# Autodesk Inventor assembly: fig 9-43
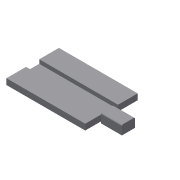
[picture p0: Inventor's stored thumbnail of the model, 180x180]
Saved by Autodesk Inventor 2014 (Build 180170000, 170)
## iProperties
Created: 2013-07
Part Number: fig 9-43
Document SubType Name: Assembly
Designer: CADCIM
Author: CADCIM
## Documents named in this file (3)
- E:\APS\Autodesk Inventor 2014-Project\inventor_2014_partfiles\Inventor_2014_prt\c09_Inv_2014_prt\c09_inv_2014_prt\fig 9-43.iam
- E:\APS\Autodesk Inventor 2014-Project\inventor_2014_partfiles\Inventor_2014_prt\c09_Inv_2014_prt\c09_inv_2014_prt\15.ipt
- E:\APS\Autodesk Inventor 2014-Project\inventor_2014_partfiles\Inventor_2014_prt\c09_Inv_2014_prt\c09_inv_2014_prt\16.ipt
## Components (2 placed, 2 different names)
1. 15:1
2. 16:1
